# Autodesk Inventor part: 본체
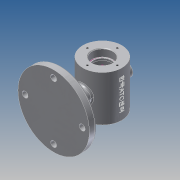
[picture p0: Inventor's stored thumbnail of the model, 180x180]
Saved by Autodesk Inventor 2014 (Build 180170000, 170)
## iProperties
Created: 2018-12
Part Number: 본체
Material: 알루미늄 6061
Document SubType Name: Modeling
Designer: kb542-14
Density: 2.71 g/cm^3
Appearance: 알루미늄 - 평지
Author: kb542-14
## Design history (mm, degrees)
sketch "스케치1"
  geometry: C1 r 30 at (0, 0); 1 further point
  constraints: 1 centre point, 1 coincident
  dimensions: "d0" = 60 diameter of C1
extrude "돌출1" new body sketch "스케치1" stored distance "d1" = 70; taper "d2" = 0 deg
node "작업 평면1"
sketch "스케치2"
  geometry: C1 r 55 at (0, 0); 1 further point
  constraints: 1 centre point, 1 coincident
  dimensions: "d4" = 110 diameter of C1
extrude "돌출2" join sketch "스케치2" distance "d5" = 11; taper "d6" = 0 deg
sketch "스케치4"
  geometry: C1 r 12 at (0, 0); 1 further point
  constraints: 1 centre point, 1 coincident
  dimensions: "d14" = 24 diameter of C1
extrude "돌출3" join sketch "스케치4" stored distance "d15" = 30; taper "d16" = 0 deg
fillet "모깎기2" dims "d18" = 3
sketch "스케치5"
  geometry: L1 (55, -64)-(-55, -64) reference; L2 (0, -64)-(-55, -64); L3 (0, -64)-(55, -64); L4 (-55, -64)-(0, -49.263); L5 (0, -49.263)-(0, -64); 1 further point
  constraints: 8 end point, 2 collinear, 1 horizontal, 1 midpoint, 1 perpendicular
  dimensions: "d19" = 55 distance of L2.start L2.end; "d20" = 180 deg angle of L2 L3 (derived); "d21" = 15 deg angle of L2 L4
revolve "회전2" sketch "스케치5" stored, may be unused: angle "d22" = 90 deg
fillet "모깎기3" dims "d23" = 3
fillet "모깎기4" dims "d24" = 3
node "작업 평면2"
sketch "스케치6"
  geometry: C1 r 10 at (0, 0); 1 further point
  constraints: 1 centre point, 1 coincident
  dimensions: "d26" = 20 diameter of C1
extrude "돌출4" join sketch "스케치6" stored distance "d27" = 30; taper "d28" = 0 deg
sketch "스케치7"
  geometry: C1 r 10 at (0, 0) reference; C2 r 5 at (0, 0)
  constraints: 1 centre point, 1 coincident
  dimensions: "d29" = 10 diameter of C2
extrude "돌출5" cut sketch "스케치7" distance "d30" = 30; taper "d31" = 0 deg
sketch "스케치8"
  geometry: C1 r 30 at (0, 0) reference; C2 r 16 at (0, 0)
  constraints: 1 centre point, 1 coincident
  dimensions: "d32" = 32 diameter of C2
extrude "돌출6" cut sketch "스케치8" distance "d33" = 12; taper "d34" = 0 deg
sketch "스케치9"
  geometry: C1 r 16 at (0, 0) reference
fillet "모깎기5" dims "d35" = 0.3
sketch "스케치10"
  geometry: C1 r 15.7 at (0, 0) reference; C2 r 14 at (0, 0)
  constraints: 1 centre point, 1 coincident
  dimensions: "d36" = 28 diameter of C2
extrude "돌출7" cut sketch "스케치10" distance "d37" = 3; taper "d38" = 0 deg
sketch "스케치11"
  geometry: C1 r 14 at (0, 0) reference; C2 r 25 at (0, 0)
  constraints: 1 centre point, 1 coincident
  dimensions: "d39" = 50 diameter of C2
extrude "돌출8" cut sketch "스케치11" distance "d40" = 40; taper "d41" = 0 deg
fillet "모깎기6" dims "d42" = 3
sketch "스케치12"
  geometry: C1 r 30 at (0, 0) reference; C2 r 16 at (0, 0)
  constraints: 1 centre point, 1 coincident
  dimensions: "d43" = 32 diameter of C2
extrude "돌출9" cut sketch "스케치12" distance "d44" = 12; taper "d45" = 0 deg
fillet "모깎기7" dims "d46" = 0.3
sketch "스케치13"
  geometry: C1 r 15.7 at (0, 0) reference; C2 r 14 at (0, 0)
  constraints: 1 centre point, 1 coincident
  dimensions: "d47" = 28 diameter of C2
extrude "돌출10" cut sketch "스케치13" distance "d48" = 3; taper "d49" = 0 deg
fillet "모깎기8" dims "d50" = 3
chamfer "모따기1" distance "d51" = 1; stored, may be unused: second distance "d52" = 2, angle "d53" = 45 deg
chamfer "모따기2" distance "d54" = 1; stored, may be unused: second distance "d55" = 2, angle "d56" = 45 deg
chamfer "모따기3" distance "d57" = 1; stored, may be unused: second distance "d58" = 2, angle "d59" = 45 deg
sketch "스케치14" dims "d60" = 88
  geometry: C1 r 55 at (0, 0) reference; C2 r 5 at (0, 0) reference; C3 r 4.5 at (0, 44); C4 r 4.5 at (-44, 0); C5 r 4.5 at (0, -44); C6 r 4.5 at (44, 0); 2 further points
  constraints: 4 centre point, 2 coincident, 1 vertical alignment, 11 other
  dimensions: "d61" = 9 diameter of C3; "d64" = 360 deg dimension on C1.centre C3.centre (derived)
extrude "돌출11" cut sketch "스케치14" distance "d66" = 10; taper "d67" = 0 deg
sketch "스케치15"
  geometry: C1 r 4.5 at (0, 0) reference; C2 r 7 at (0, 0); 1 further point
  constraints: 1 centre point, 1 coincident
  dimensions: "d68" = 14 diameter of C2
extrude "돌출12" cut sketch "스케치15" distance "d69" = 10; taper "d70" = 0 deg
sketch "스케치16"
  geometry: C1 r 4.5 at (0, 0) reference; C2 r 7 at (0, 0); 1 further point
  constraints: 1 centre point, 1 coincident
  dimensions: "d71" = 14 diameter of C2
extrude "돌출13" cut sketch "스케치16" distance "d72" = 10; taper "d73" = 0 deg
sketch "스케치17"
  geometry: C1 r 4.5 at (0, 0) reference; C2 r 7 at (0, 0); 1 further point
  constraints: 1 centre point, 1 coincident
  dimensions: "d74" = 14 diameter of C2
extrude "돌출14" cut sketch "스케치17" distance "d75" = 10; taper "d76" = 0 deg
sketch "스케치18"
  geometry: C1 r 4.5 at (0, 0) reference; C2 r 7 at (0, 0); 1 further point
  constraints: 1 centre point, 1 coincident
  dimensions: "d77" = 14 diameter of C2
extrude "돌출15" cut sketch "스케치18" distance "d78" = 10; taper "d79" = 0 deg
fillet "모깎기9" dims "d80" = 3
sketch "스케치19" dims "d81" = 46
  geometry: C1 r 17 at (0, 0) reference; 2 further points
  constraints: 1 coincident, 1 vertical alignment, 2 other
hole "구멍1" sketch "스케치19" at (0, 23) diameter "d82" = 3.242; stored, may be unused: countersink angle "d86" = 90 deg, drill point angle "d88" = 118 deg; dims "d83" = 8, "d84" = 4, "d85" = 2, "d87" = 10
sketch "스케치20"
  geometry: C1 r 17 at (0, 0) reference; C2 r 23 at (0, 0); C3 r 1.621 at (0, 23) reference; 1 further point
  constraints: 2 coincident, 1 centre point
  dimensions: "d92" = 46 diameter of C2
hole "구멍2" sketch "스케치20" at (0, 23) diameter "d93" = 3.242; stored, may be unused: countersink angle "d97" = 90 deg, drill point angle "d99" = 118 deg; dims "d94" = 8, "d95" = 4, "d96" = 2, "d98" = 10
node "작업 평면3"
sketch "스케치21"
  geometry: L1 (30, 35)-(-30, 35) reference; L2 (3.602, 24.848)-(3.602, -24.848); L3 (3.602, -24.848)-(-3.602, -24.848); L4 (-3.602, -24.848)-(-3.602, 24.848); L5 (-3.602, 24.848)-(3.602, 24.848); 4 further points
  constraints: 2 midpoint, 1 horizontal alignment, 1 vertical alignment, 2 other
  dimensions: "d104" = 35 distance from line of L1 point (0, 0); "d105" = 30 horizontal distance of L1.start point (0, 0)
feature "엠보싱1" sketch "스케치21" dims "d0" = 60, "d19" = 55, "d20" = 180 deg (derived), "d21" = 15 deg, "d106" = 0.5, "d107" = 0
node "솔리드1"
pattern_circular "원형 패턴1" dims angle "d90" = 360 deg
pattern_circular "원형 패턴2" dims angle "d101" = 360 deg
other parameters: "d3" = -75, "d25" = 37, "d103" = 31
